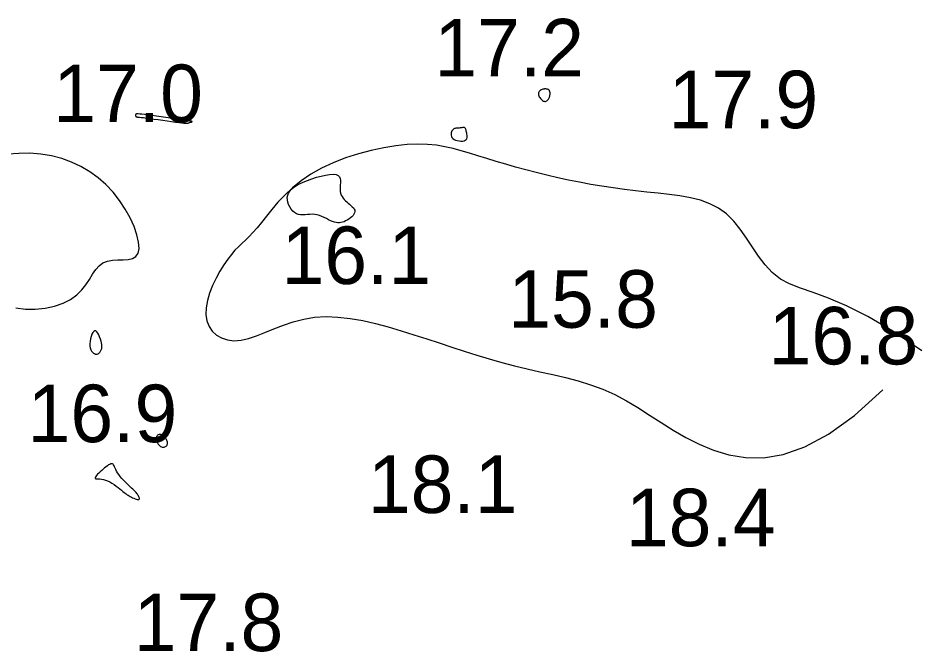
# Model space of a CAD drawing. Extents: x 3040093 to 3056816, y 408076 to 509144.
# Drawn here: x 3045487.4 to 3045566, y 433720.4 to 433775.5 of the extents above; entities that cross this region are included whole.
import ezdxf

# ---------------------------------------------------------------- set-up
doc = ezdxf.new("R2010")
doc.units = 0
doc.layers.add('V-CHAN-CONT-EL17', color=7, linetype='Continuous')
doc.layers.add('V-TOPO-SOUN-0610', color=7, linetype='Continuous')

msp = doc.modelspace()

# ---------------------------------------------------------------- linework, layer by layer
at = {"layer": 'V-CHAN-CONT-EL17'}
for points in [[(3045533.591, 433768.542), (3045533.615, 433768.596), (3045533.634, 433768.65), (3045533.649, 433768.704), (3045533.66, 433768.757), (3045533.668, 433768.81), (3045533.673, 433768.862), (3045533.675, 433768.912), (3045533.675, 433768.962), (3045533.672, 433769.01), (3045533.665, 433769.055), (3045533.656, 433769.098), (3045533.642, 433769.139), (3045533.625, 433769.176), (3045533.602, 433769.209), (3045533.574, 433769.237), (3045533.541, 433769.262), (3045533.503, 433769.281), (3045533.46, 433769.297), (3045533.414, 433769.309), (3045533.365, 433769.316), (3045533.313, 433769.321), (3045533.26, 433769.322), (3045533.205, 433769.319), (3045533.15, 433769.314), (3045533.095, 433769.306), (3045533.041, 433769.294), (3045532.988, 433769.279), (3045532.937, 433769.259), (3045532.888, 433769.235), (3045532.842, 433769.206), (3045532.799, 433769.172), (3045532.761, 433769.133), (3045532.728, 433769.088), (3045532.701, 433769.039), (3045532.681, 433768.985), (3045532.67, 433768.926), (3045532.669, 433768.863), (3045532.679, 433768.796), (3045532.7, 433768.724), (3045532.734, 433768.65), (3045532.778, 433768.574), (3045532.832, 433768.5), (3045532.892, 433768.43), (3045532.957, 433768.367), (3045533.025, 433768.314), (3045533.094, 433768.273), (3045533.162, 433768.247), (3045533.226, 433768.239), (3045533.287, 433768.245), (3045533.344, 433768.265), (3045533.397, 433768.296), (3045533.445, 433768.336), (3045533.489, 433768.383), (3045533.528, 433768.434), (3045533.562, 433768.488)], [(3045497.732, 433766.891), (3045497.762, 433766.886), (3045497.809, 433766.88), (3045497.88, 433766.874), (3045497.982, 433766.863), (3045498.125, 433766.848), (3045498.315, 433766.825), (3045498.559, 433766.794), (3045498.863, 433766.754), (3045499.213, 433766.706), (3045499.593, 433766.653), (3045499.99, 433766.598), (3045500.385, 433766.543), (3045500.765, 433766.491), (3045501.112, 433766.445), (3045501.411, 433766.407), (3045501.651, 433766.379), (3045501.835, 433766.361), (3045501.974, 433766.351), (3045502.075, 433766.349), (3045502.147, 433766.351), (3045502.198, 433766.358), (3045502.239, 433766.369), (3045502.276, 433766.381), (3045502.318, 433766.394), (3045502.363, 433766.407), (3045502.409, 433766.42), (3045502.452, 433766.433), (3045502.49, 433766.446), (3045502.521, 433766.459), (3045502.541, 433766.471), (3045502.549, 433766.482), (3045502.541, 433766.493), (3045502.52, 433766.503), (3045502.489, 433766.512), (3045502.449, 433766.52), (3045502.404, 433766.528), (3045502.356, 433766.535), (3045502.307, 433766.541), (3045502.261, 433766.547), (3045502.218, 433766.552), (3045502.171, 433766.559), (3045502.112, 433766.567), (3045502.031, 433766.578), (3045501.921, 433766.594), (3045501.773, 433766.615), (3045501.578, 433766.643), (3045501.328, 433766.679), (3045501.017, 433766.725), (3045500.659, 433766.776), (3045500.27, 433766.833), (3045499.866, 433766.89), (3045499.462, 433766.947), (3045499.076, 433767.001), (3045498.724, 433767.049), (3045498.421, 433767.088), (3045498.181, 433767.117), (3045497.999, 433767.136), (3045497.866, 433767.147), (3045497.774, 433767.151), (3045497.716, 433767.149), (3045497.682, 433767.143), (3045497.665, 433767.134), (3045497.655, 433767.123), (3045497.647, 433767.112), (3045497.64, 433767.1), (3045497.633, 433767.088), (3045497.626, 433767.075), (3045497.621, 433767.062), (3045497.618, 433767.048), (3045497.617, 433767.032), (3045497.618, 433767.016), (3045497.622, 433767), (3045497.628, 433766.982), (3045497.637, 433766.965), (3045497.648, 433766.948), (3045497.661, 433766.932), (3045497.676, 433766.918), (3045497.693, 433766.906), (3045497.711, 433766.897)], [(3045526.379, 433764.922), (3045526.429, 433764.998), (3045526.457, 433765.086), (3045526.466, 433765.181), (3045526.462, 433765.282), (3045526.448, 433765.382), (3045526.429, 433765.48), (3045526.409, 433765.572), (3045526.392, 433765.653), (3045526.377, 433765.725), (3045526.362, 433765.787), (3045526.346, 433765.839), (3045526.327, 433765.882), (3045526.303, 433765.916), (3045526.273, 433765.94), (3045526.235, 433765.956), (3045526.187, 433765.964), (3045526.132, 433765.965), (3045526.069, 433765.96), (3045526.002, 433765.952), (3045525.93, 433765.941), (3045525.855, 433765.929), (3045525.779, 433765.919), (3045525.703, 433765.911), (3045525.629, 433765.906), (3045525.557, 433765.903), (3045525.487, 433765.898), (3045525.419, 433765.888), (3045525.355, 433765.872), (3045525.295, 433765.845), (3045525.239, 433765.806), (3045525.187, 433765.752), (3045525.141, 433765.68), (3045525.103, 433765.594), (3045525.076, 433765.497), (3045525.064, 433765.395), (3045525.07, 433765.29), (3045525.097, 433765.187), (3045525.148, 433765.09), (3045525.227, 433765.004), (3045525.335, 433764.93), (3045525.466, 433764.871), (3045525.612, 433764.828), (3045525.766, 433764.8), (3045525.92, 433764.789), (3045526.066, 433764.795), (3045526.196, 433764.819), (3045526.302, 433764.862)], [(3045510.861, 433760.09), (3045510.933, 433760.273), (3045511.044, 433760.447), (3045511.195, 433760.613), (3045511.387, 433760.772), (3045511.62, 433760.927), (3045511.896, 433761.077), (3045512.214, 433761.226), (3045512.574, 433761.374), (3045512.962, 433761.514), (3045513.365, 433761.642), (3045513.766, 433761.752), (3045514.152, 433761.836), (3045514.507, 433761.889), (3045514.816, 433761.905), (3045515.065, 433761.877), (3045515.243, 433761.802), (3045515.358, 433761.685), (3045515.422, 433761.536), (3045515.447, 433761.362), (3045515.446, 433761.171), (3045515.432, 433760.972), (3045515.415, 433760.773), (3045515.41, 433760.582), (3045515.424, 433760.407), (3045515.46, 433760.246), (3045515.514, 433760.099), (3045515.586, 433759.963), (3045515.671, 433759.837), (3045515.77, 433759.718), (3045515.879, 433759.606), (3045515.997, 433759.498), (3045516.121, 433759.393), (3045516.245, 433759.289), (3045516.365, 433759.187), (3045516.475, 433759.085), (3045516.569, 433758.982), (3045516.642, 433758.878), (3045516.688, 433758.772), (3045516.702, 433758.663), (3045516.679, 433758.55), (3045516.624, 433758.436), (3045516.541, 433758.322), (3045516.436, 433758.212), (3045516.314, 433758.107), (3045516.181, 433758.009), (3045516.041, 433757.92), (3045515.9, 433757.844), (3045515.762, 433757.781), (3045515.626, 433757.733), (3045515.491, 433757.701), (3045515.355, 433757.684), (3045515.215, 433757.685), (3045515.071, 433757.702), (3045514.919, 433757.738), (3045514.76, 433757.792), (3045514.59, 433757.865), (3045514.411, 433757.95), (3045514.224, 433758.043), (3045514.03, 433758.138), (3045513.83, 433758.227), (3045513.627, 433758.306), (3045513.42, 433758.369), (3045513.211, 433758.408), (3045513.001, 433758.422), (3045512.792, 433758.416), (3045512.584, 433758.399), (3045512.38, 433758.381), (3045512.18, 433758.369), (3045511.985, 433758.373), (3045511.798, 433758.402), (3045511.619, 433758.465), (3045511.45, 433758.567), (3045511.293, 433758.705), (3045511.154, 433758.872), (3045511.034, 433759.061), (3045510.938, 433759.264), (3045510.87, 433759.476), (3045510.831, 433759.688), (3045510.828, 433759.894)], [(3045494.635, 433746.632), (3045494.662, 433746.686), (3045494.685, 433746.744), (3045494.701, 433746.811), (3045494.71, 433746.89), (3045494.709, 433746.984), (3045494.696, 433747.099), (3045494.67, 433747.237), (3045494.629, 433747.4), (3045494.574, 433747.578), (3045494.508, 433747.76), (3045494.434, 433747.933), (3045494.352, 433748.085), (3045494.264, 433748.204), (3045494.174, 433748.278), (3045494.083, 433748.294), (3045493.993, 433748.245), (3045493.908, 433748.138), (3045493.83, 433747.986), (3045493.762, 433747.801), (3045493.708, 433747.595), (3045493.67, 433747.379), (3045493.652, 433747.167), (3045493.657, 433746.969), (3045493.687, 433746.797), (3045493.738, 433746.651), (3045493.806, 433746.529), (3045493.886, 433746.432), (3045493.973, 433746.357), (3045494.063, 433746.304), (3045494.151, 433746.271), (3045494.233, 433746.258), (3045494.305, 433746.262), (3045494.367, 433746.283), (3045494.42, 433746.316), (3045494.466, 433746.359), (3045494.506, 433746.409), (3045494.542, 433746.465), (3045494.575, 433746.522), (3045494.605, 433746.578)], [(3045500.332, 433738.297), (3045500.365, 433738.348), (3045500.387, 433738.406), (3045500.399, 433738.468), (3045500.401, 433738.536), (3045500.394, 433738.607), (3045500.377, 433738.681), (3045500.351, 433738.757), (3045500.316, 433738.834), (3045500.272, 433738.911), (3045500.222, 433738.985), (3045500.165, 433739.054), (3045500.102, 433739.118), (3045500.035, 433739.173), (3045499.965, 433739.218), (3045499.892, 433739.251), (3045499.818, 433739.271), (3045499.744, 433739.278), (3045499.673, 433739.27), (3045499.608, 433739.249), (3045499.549, 433739.215), (3045499.501, 433739.167), (3045499.464, 433739.106), (3045499.441, 433739.032), (3045499.434, 433738.945), (3045499.442, 433738.849), (3045499.464, 433738.747), (3045499.498, 433738.644), (3045499.542, 433738.543), (3045499.596, 433738.448), (3045499.658, 433738.363), (3045499.727, 433738.292), (3045499.8, 433738.238), (3045499.876, 433738.2), (3045499.954, 433738.178), (3045500.03, 433738.17), (3045500.104, 433738.174), (3045500.173, 433738.191), (3045500.235, 433738.217), (3045500.289, 433738.253)], [(3045494.128, 433735.453), (3045494.184, 433735.432), (3045494.269, 433735.422), (3045494.38, 433735.416), (3045494.513, 433735.408), (3045494.665, 433735.392), (3045494.831, 433735.362), (3045495.009, 433735.313), (3045495.194, 433735.24), (3045495.383, 433735.146), (3045495.572, 433735.036), (3045495.759, 433734.916), (3045495.94, 433734.79), (3045496.111, 433734.664), (3045496.27, 433734.542), (3045496.411, 433734.43), (3045496.535, 433734.331), (3045496.642, 433734.245), (3045496.737, 433734.17), (3045496.824, 433734.103), (3045496.907, 433734.042), (3045496.988, 433733.987), (3045497.073, 433733.934), (3045497.164, 433733.881), (3045497.264, 433733.828), (3045497.371, 433733.777), (3045497.48, 433733.728), (3045497.588, 433733.686), (3045497.689, 433733.652), (3045497.78, 433733.629), (3045497.856, 433733.62), (3045497.914, 433733.626), (3045497.951, 433733.649), (3045497.967, 433733.688), (3045497.966, 433733.739), (3045497.95, 433733.8), (3045497.922, 433733.868), (3045497.884, 433733.94), (3045497.839, 433734.013), (3045497.789, 433734.085), (3045497.737, 433734.152), (3045497.682, 433734.218), (3045497.62, 433734.285), (3045497.552, 433734.355), (3045497.474, 433734.432), (3045497.386, 433734.517), (3045497.284, 433734.613), (3045497.168, 433734.724), (3045497.036, 433734.85), (3045496.893, 433734.99), (3045496.743, 433735.14), (3045496.591, 433735.298), (3045496.443, 433735.46), (3045496.302, 433735.623), (3045496.175, 433735.785), (3045496.065, 433735.942), (3045495.977, 433736.091), (3045495.907, 433736.229), (3045495.851, 433736.355), (3045495.805, 433736.467), (3045495.763, 433736.562), (3045495.721, 433736.639), (3045495.675, 433736.694), (3045495.621, 433736.726), (3045495.553, 433736.733), (3045495.474, 433736.717), (3045495.384, 433736.68), (3045495.284, 433736.625), (3045495.176, 433736.554), (3045495.06, 433736.47), (3045494.939, 433736.373), (3045494.813, 433736.268), (3045494.684, 433736.156), (3045494.556, 433736.042), (3045494.435, 433735.927), (3045494.326, 433735.817), (3045494.233, 433735.714), (3045494.162, 433735.623), (3045494.118, 433735.547), (3045494.105, 433735.49)]]:
    msp.add_lwpolyline(points, close=True, dxfattribs=at)
for points in [[(3045566.016, 433746.544), (3045563.485, 433748.248), (3045561.311, 433749.526), (3045559.458, 433750.457), (3045557.888, 433751.125), (3045556.565, 433751.611), (3045555.452, 433751.997), (3045554.512, 433752.364), (3045553.708, 433752.796), (3045553.006, 433753.353), (3045552.382, 433754.022), (3045551.813, 433754.768), (3045551.277, 433755.557), (3045550.753, 433756.354), (3045550.218, 433757.126), (3045549.65, 433757.838), (3045549.027, 433758.457), (3045548.332, 433758.955), (3045547.57, 433759.343), (3045546.749, 433759.639), (3045545.879, 433759.859), (3045544.97, 433760.022), (3045544.029, 433760.146), (3045543.068, 433760.248), (3045542.095, 433760.346), (3045541.117, 433760.454), (3045540.139, 433760.576), (3045539.161, 433760.712), (3045538.185, 433760.862), (3045537.214, 433761.025), (3045536.248, 433761.203), (3045535.289, 433761.394), (3045534.339, 433761.599), (3045533.4, 433761.818), (3045532.475, 433762.048), (3045531.567, 433762.286), (3045530.68, 433762.53), (3045529.818, 433762.777), (3045528.982, 433763.024), (3045528.178, 433763.269), (3045527.408, 433763.507), (3045526.672, 433763.737), (3045525.959, 433763.951), (3045525.252, 433764.142), (3045524.535, 433764.302), (3045523.794, 433764.424), (3045523.012, 433764.501), (3045522.173, 433764.524), (3045521.262, 433764.486), (3045520.27, 433764.382), (3045519.214, 433764.212), (3045518.118, 433763.977), (3045517.005, 433763.68), (3045515.9, 433763.324), (3045514.825, 433762.909), (3045513.805, 433762.437), (3045512.863, 433761.912), (3045512.018, 433761.337), (3045511.266, 433760.726), (3045510.598, 433760.096), (3045510.004, 433759.463), (3045509.476, 433758.844), (3045509.004, 433758.255), (3045508.58, 433757.713), (3045508.194, 433757.234), (3045507.837, 433756.829), (3045507.503, 433756.483), (3045507.186, 433756.177), (3045506.88, 433755.889), (3045506.578, 433755.6), (3045506.275, 433755.289), (3045505.965, 433754.936), (3045505.641, 433754.521), (3045505.302, 433754.03), (3045504.959, 433753.473), (3045504.629, 433752.867), (3045504.329, 433752.229), (3045504.074, 433751.577), (3045503.881, 433750.927), (3045503.767, 433750.296), (3045503.747, 433749.702), (3045503.834, 433749.158), (3045504.023, 433748.676), (3045504.306, 433748.261), (3045504.672, 433747.922), (3045505.113, 433747.666), (3045505.621, 433747.5), (3045506.186, 433747.433), (3045506.8, 433747.471), (3045507.454, 433747.616), (3045508.148, 433747.847), (3045508.884, 433748.135), (3045509.661, 433748.453), (3045510.481, 433748.773), (3045511.344, 433749.068), (3045512.251, 433749.309), (3045513.203, 433749.469), (3045514.199, 433749.527), (3045515.233, 433749.489), (3045516.299, 433749.368), (3045517.389, 433749.176), (3045518.496, 433748.925), (3045519.612, 433748.629), (3045520.73, 433748.3), (3045521.844, 433747.951), (3045522.947, 433747.593), (3045524.042, 433747.232), (3045525.129, 433746.872), (3045526.214, 433746.518), (3045527.297, 433746.174), (3045528.383, 433745.844), (3045529.474, 433745.534), (3045530.573, 433745.247), (3045531.681, 433744.985), (3045532.794, 433744.736), (3045533.909, 433744.488), (3045535.018, 433744.225), (3045536.119, 433743.934), (3045537.204, 433743.6), (3045538.27, 433743.211), (3045539.31, 433742.75), (3045540.325, 433742.211), (3045541.324, 433741.61), (3045542.325, 433740.968), (3045543.343, 433740.308), (3045544.392, 433739.652), (3045545.489, 433739.021), (3045546.649, 433738.438), (3045547.888, 433737.925), (3045549.221, 433737.511), (3045550.665, 433737.261), (3045552.237, 433737.244), (3045553.954, 433737.532), (3045555.832, 433738.196), (3045557.89, 433739.307), (3045560.143, 433740.936), (3045562.61, 433743.153)], [(3045487.205, 433750.275), (3045488.045, 433750.185), (3045488.908, 433750.186), (3045489.762, 433750.274), (3045490.579, 433750.444), (3045491.33, 433750.693), (3045491.984, 433751.015), (3045492.521, 433751.405), (3045492.956, 433751.841), (3045493.315, 433752.303), (3045493.62, 433752.767), (3045493.897, 433753.211), (3045494.169, 433753.613), (3045494.461, 433753.951), (3045494.798, 433754.201), (3045495.195, 433754.351), (3045495.636, 433754.424), (3045496.097, 433754.452), (3045496.554, 433754.467), (3045496.983, 433754.501), (3045497.359, 433754.586), (3045497.658, 433754.755), (3045497.856, 433755.039), (3045497.934, 433755.462), (3045497.895, 433756.006), (3045497.748, 433756.645), (3045497.501, 433757.353), (3045497.162, 433758.103), (3045496.739, 433758.87), (3045496.242, 433759.625), (3045495.679, 433760.344), (3045495.056, 433761.004), (3045494.38, 433761.598), (3045493.653, 433762.124), (3045492.879, 433762.579), (3045492.062, 433762.963), (3045491.206, 433763.271), (3045490.315, 433763.502), (3045489.392, 433763.654), (3045488.443, 433763.725), (3045487.478, 433763.719), (3045486.51, 433763.64)]]:
    msp.add_lwpolyline(points, dxfattribs=at)

# ---------------------------------------------------------------- texts
at = {"layer": 'V-TOPO-SOUN-0610'}
for s, p in [('17.2 ', (3045523.613, 433770.41)), ('17.0 ', (3045490.473, 433766.44)), ('17.9 ', (3045543.983, 433765.91)), ('16.1 ', (3045510.323, 433752.36)), ('15.8 ', (3045530.043, 433748.56)), ('16.8 ', (3045552.683, 433745.37)), ('16.9 ', (3045488.243, 433738.61)), ('18.1 ', (3045517.833, 433732.45)), ('18.4 ', (3045540.273, 433729.56)), ('17.8 ', (3045497.463, 433720.44))]:
    msp.add_text(s, height=5, dxfattribs=at).set_placement(p)

doc.saveas('drawing.dxf')
